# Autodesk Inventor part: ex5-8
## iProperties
Shininess: 64.0
Length Units: 11272
Angle Units: 11279
Time Units: 11290
Mass Units: 11286
Length Display Precision: 3
Angle Display Precision: 2
Compacted: True
Part Number: ex5-8
Document SubType Name: Modeling
Created: 2002-09
Designer: Elise Moss
Density: 0.0
Volumn: 0.0
Area: 0.0
PropertySet Name: Model Information
Control State: 0
Master: False
Checked Out: False
Author: Elise Moss
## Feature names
1. Revolution1
2. Hole1
3. Shell1
4. Loft1
5. Sweep1
6. Coil1
